Omron CX-Programmer project NouvProjet (CX-Programmer 9.31)

# PLC NouvAPI1: CJ1M CPU23

## Program NouvProgramme1 (cyclic task 0)

### Section Section1

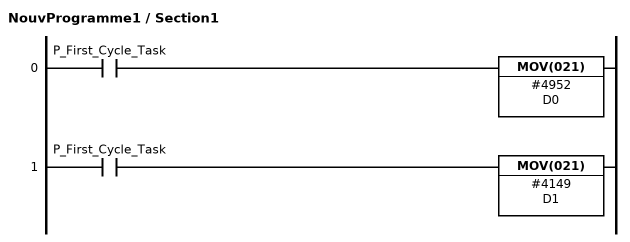
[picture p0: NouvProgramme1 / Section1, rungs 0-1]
; rung 0
LD P_First_Cycle_Task
MOV(021) #4952 D0
; rung 1
LD P_First_Cycle_Task
MOV(021) #4149 D1

### Section END
; rung 0
END(001)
